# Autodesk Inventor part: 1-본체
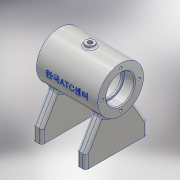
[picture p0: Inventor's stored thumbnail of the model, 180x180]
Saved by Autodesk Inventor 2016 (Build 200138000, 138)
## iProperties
Created: 2018-05
Part Number: 1-본체
Material: 알루미늄 6061
Document SubType Name: Modeling
Designer: 201-25
Density: 2.7 g/cm^3
Appearance: 알루미늄 - 평지
Mass: 317.85 g
Surface Area: 375.672 cm^2
Volume: 117.722 cm^3
Author: 201-25
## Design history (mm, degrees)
sketch "스케치1"
  geometry: L1 (-35, 26)-(35, 26); L2 (35, 26)-(35, 0); L3 (35, 0)-(-35, 0); L4 (-35, 0)-(-35, 26); 2 further points
  constraints: 8 end point, 2 midpoint, 2 parallel, 1 horizontal, 1 perpendicular, 1 vertical alignment
  dimensions: "d0" = 52 diameter of L1 L3; "d1" = 70 distance of L1.start L1.end
revolve "회전1" sketch "스케치1" stored, may be unused: angle "d2" = 90 deg
node "작업 평면1"
sketch "스케치3"
  geometry: L1 (-11.906, -10)-(-35, -50); L2 (-35, -50)-(-35, -65); L3 (-35, -65)-(35, -65); L4 (35, -65)-(35, -50); L5 (35, -50)-(11.906, -10); L6 (11.906, -10)-(-11.906, -10); 3 further points
  constraints: 12 end point, 3 perpendicular, 2 midpoint, 2 vertical alignment, 1 horizontal alignment, 1 vertical
  dimensions: "d12" = 70 distance of L2.end L3.end; "d13" = 15 distance of L3.end L4.end; "d14" = 30 deg angle of L4 L5; "d15" = 55 distance between parallel lines of L3 L6; "d16" = 65 distance from line of L3 point (0, 0)
extrude "돌출1" join sketch "스케치3" stored distance "d17" = 10; taper "d18" = 0 deg
sketch "스케치2"
  geometry: L1 (35, 26)-(35, -26) reference; L2 (35, 0)-(23, 0); L3 (23, 0)-(23, -16); L4 (23, -16)-(35, -16); L5 (35, -16)-(35, 0); L6 (23, 0)-(21, 0); L7 (21, 0)-(21, -14); L8 (21, -14)-(23, -14); L9 (23, -14)-(23, 0); L10 (21, 0)-(-21, 0); L11 (-21, 0)-(-21, -21); L12 (-21, -21)-(21, -21); L13 (21, -21)-(21, 0); L14 (-21, 0)-(-23, 0); L15 (-23, 0)-(-23, -14); L16 (-23, -14)-(-21, -14); L17 (-21, -14)-(-21, 0); L18 (-35, 26)-(-35, -26) reference; L19 (-23, 0)-(-35, 0); L20 (-35, 0)-(-35, -16); L21 (-35, -16)-(-23, -16); L22 (-23, -16)-(-23, 0); 1 further point
  constraints: 40 end point, 10 parallel, 5 horizontal, 5 perpendicular, 2 collinear, 1 midpoint, 1 point on line
  dimensions: "d3" = 32 diameter of L4 L2; "d4" = 28 diameter of L8 L10; "d5" = 42 diameter of L12 L10; "d6" = 42 distance of L11.end L12.end; "d7" = 12 distance of L3.end L4.end; "d8" = 2 distance of L15.end L16.end; "d9" = 12 distance of L20.end L21.end
revolve "회전2" sketch "스케치2" stored, may be unused: angle "d10" = 90 deg
node "작업 평면2"
sketch "스케치4"
  geometry: C1 r 5 at (0, 0); 1 further point
  constraints: 1 centre point, 1 coincident
  dimensions: "d20" = 10 diameter of C1
extrude "돌출2" join sketch "스케치4" stored distance "d21" = 10; taper "d22" = 0 deg
sketch "스케치5"
  geometry: L1 (0, 0)-(0, -26.253); L2 (0, 0)-(8.893, -24.432); A1 r 26 centre (0, 0) between (-17.325, -19.386) and (17.325, -19.386) reference; 1 further point
  constraints: 4 end point, 1 coincident, 1 point on circle, 1 vertical
  dimensions: "d24" = 20 deg angle of L1 L2
node "작업 평면4"
  node "작업 평면3"
sketch "스케치7"
  geometry: C1 r 6 at (0, 0); 1 further point
  constraints: 1 centre point, 1 coincident
  dimensions: "d26" = 12 diameter of C1
extrude "돌출3" join sketch "스케치7" stored distance "d27" = 10; taper "d28" = 0 deg
sketch "스케치8"
  geometry: 1 further point
hole "구멍1" sketch "스케치8" at (0, 0) diameter "d29" = 5.188; stored, may be unused: countersink angle "d33" = 90 deg, drill point angle "d35" = 118 deg; dims "d30" = 12, "d31" = 4, "d32" = 2, "d34" = 16
sketch "스케치9"
  geometry: 1 further point
hole "구멍2" sketch "스케치9" at (0, 0) diameter "d36" = 5.188; stored, may be unused: countersink angle "d40" = 90 deg, drill point angle "d42" = 118 deg; dims "d37" = 12, "d38" = 4, "d39" = 2, "d41" = 16
sketch "스케치10"
  geometry: L1 (0, 0)-(-21, 0)
  constraints: 2 end point, 1 horizontal
  dimensions: "d43" = 21 distance of L1.start L1.end
hole "구멍3" sketch "스케치10" at (-21, 0) diameter "d44" = 3.242; stored, may be unused: countersink angle "d48" = 90 deg, drill point angle "d50" = 118 deg; dims "d45" = 8, "d46" = 4, "d47" = 2, "d49" = 10
sketch "스케치11"
  geometry: L1 (5, -15)-(55, -15); L2 (55, -15)-(55, -55); L3 (55, -55)-(5, -55); L4 (5, -55)-(5, -15); L5 (5, -15)-(55, -55); L6 (55, -15)-(5, -55); 2 further points
  constraints: 12 end point, 2 midpoint, 2 parallel, 1 coincident, 1 horizontal, 1 perpendicular
  dimensions: "d54" = 40 distance of L1.end L2.end; "d55" = 50 distance of L2.end L3.end
hole "구멍4" sketch "스케치11" at (55, -15), (5, -15), (5, -55), (55, -55) diameter "d56" = 4.134; stored, may be unused: countersink angle "d60" = 90 deg, drill point angle "d62" = 118 deg; dims "d57" = 8, "d58" = 4, "d59" = 2, "d61" = 10
fillet "모깎기1" dims "d63" = 3
fillet "모깎기2" dims "d64" = 3
fillet "모깎기3" dims "d65" = 3
chamfer "모따기1" distance "d66" = 1; stored, may be unused: second distance "d67" = 2, angle "d68" = 45 deg
fillet "모깎기4" dims "d69" = 2
sketch "스케치12"
  geometry: L1 (-58, 39)-(-58, 91) reference; L2 (-58, 91)-(12, 91) reference; 2 further points
  constraints: 1 other
  dimensions: "d70" = 35 distance from line of L1 point (-23, 65); "d71" = 26 distance from line of point (-23, 65) L2
feature "엠보싱1" sketch "스케치12" dims "d0" = 52, "d1" = 70, "d72" = 0.5, "d73" = 0
fillet "모깎기5" dims "d74" = 0.3
node "솔리드1"
mirror "대칭1"
pattern_circular "원형 패턴1" dims angle "d52" = 360 deg
mirror "대칭2"
other parameters: "d11" = 25, "d19" = 29, "d25" = 3
